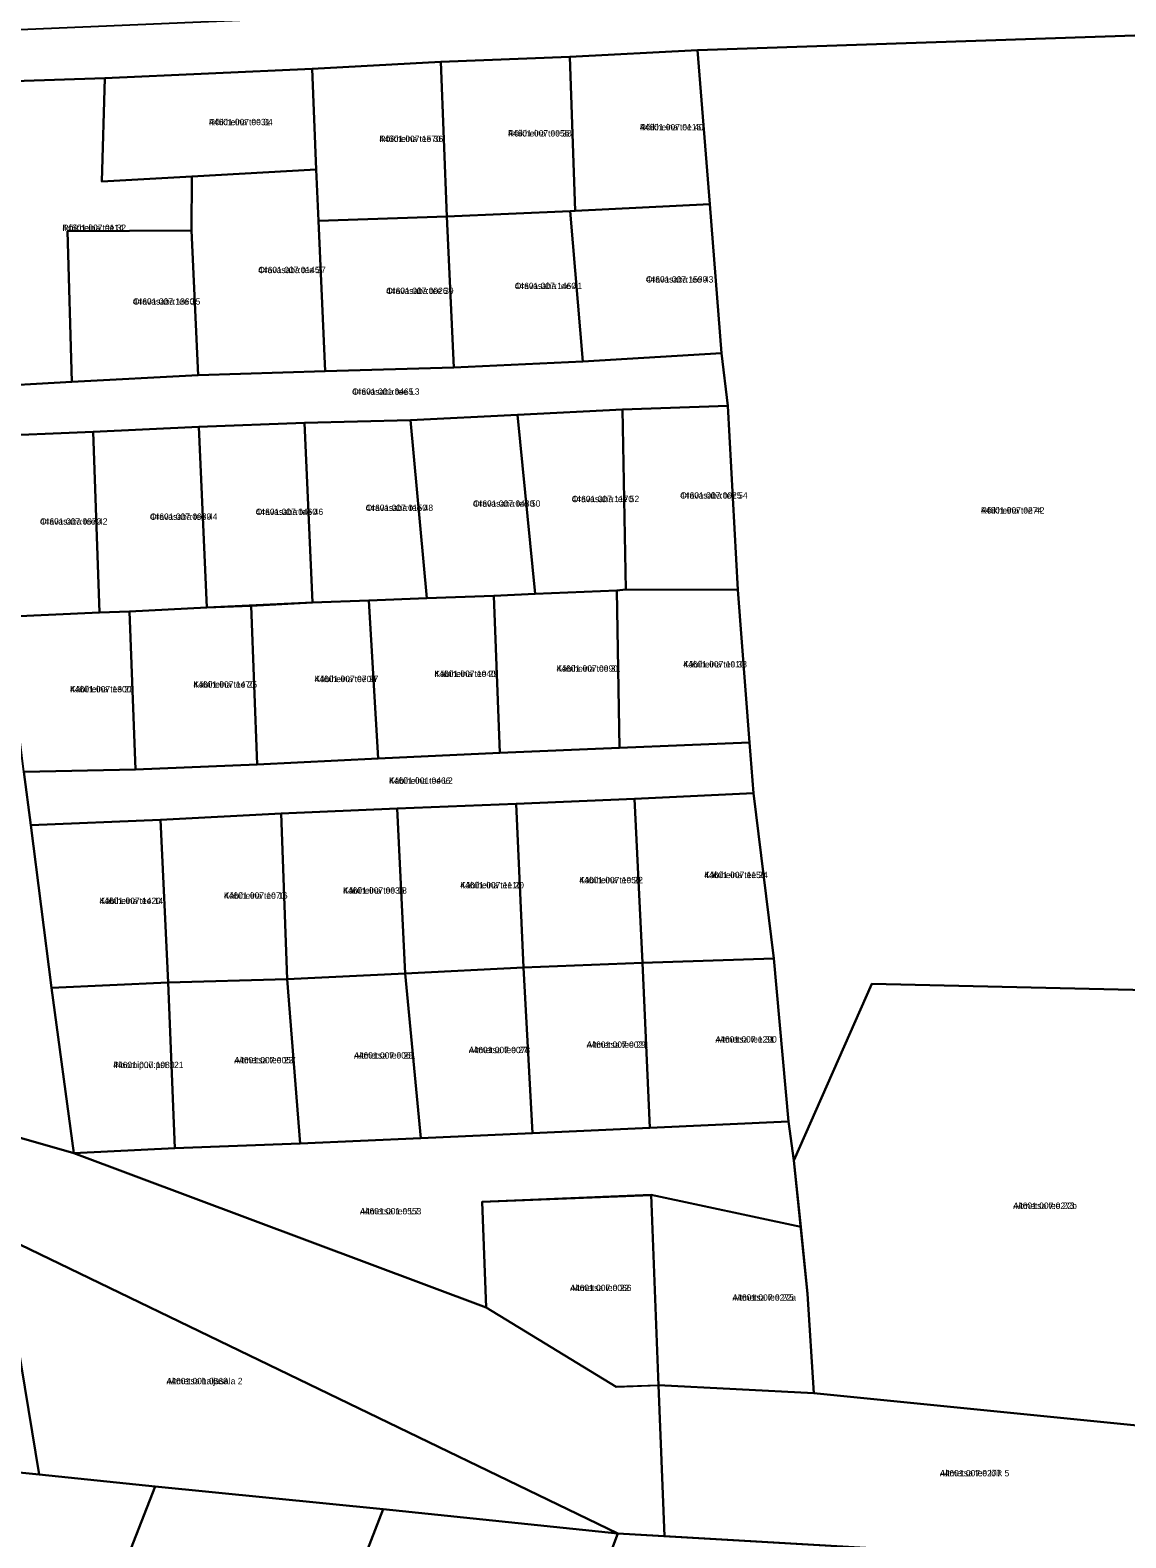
# Model space of a CAD drawing. Extents: x 551843 to 558501, y 6589003 to 6595718.
# Drawn here: x 554119.5 to 554378.5, y 6592353.3 to 6592709.8 of the extents above; entities that cross this region are included whole.
import ezdxf

# ---------------------------------------------------------------- set-up
doc = ezdxf.new("R2010")
doc.units = 0
for name, color, linetype in [('L_AADRESS', 7, 'Continuous'), ('PIIR', 7, 'Continuous'), ('TUNNUS', 7, 'Continuous')]:
    doc.layers.add(name, color=color, linetype=linetype)

msp = doc.modelspace()

# ---------------------------------------------------------------- linework, layer by layer
at = {"layer": 'PIIR'}
for points in [[(554096.53, 6592697.08), (554093.97, 6592709.01), (554118.91, 6592710.02), (554144.94, 6592711.06), (554170.97, 6592712.22), (554197.07, 6592713.42), (554222.84, 6592714.47), (554247.74, 6592715.45), (554276.46, 6592716.41), (554286.44, 6592717.06), (554411.66, 6592724.59), (554411.2, 6592709.5), (554277.28, 6592705.03), (554247.08, 6592703.49), (554216.6, 6592702.26), (554186.13, 6592700.61), (554137.12, 6592698.41)], [(554277.28, 6592705.03), (554411.2, 6592709.5), (554410.15, 6592675.78), (554409.09, 6592641.51), (554408.12, 6592610.02), (554407.21, 6592580.64), (554406.4, 6592554.65), (554405.5, 6592525.38), (554404.66, 6592498.07), (554404.12, 6592482.32), (554318.46, 6592484.32), (554300.06, 6592442.55), (554298.78, 6592451.79), (554295.27, 6592490.33), (554290.49, 6592529.36), (554289.57, 6592541.38), (554286.82, 6592577.47), (554284.43, 6592620.98), (554282.94, 6592633.43), (554280.18, 6592668.59)], [(554247.08, 6592703.49), (554277.28, 6592705.03), (554280.18, 6592668.59), (554248.31, 6592667.05)], [(554216.6, 6592702.26), (554217.99, 6592665.7), (554187.65, 6592664.68), (554187.14, 6592676.79), (554186.13, 6592700.61)], [(554247.08, 6592703.49), (554248.31, 6592667.05), (554247.18, 6592667), (554217.99, 6592665.7), (554216.6, 6592702.26)], [(554096.53, 6592697.08), (554137.12, 6592698.41), (554136.47, 6592673.96), (554157.71, 6592675.13), (554157.61, 6592662.43), (554128.31, 6592662.26), (554129.3, 6592626.64), (554106.93, 6592625.38)], [(554186.13, 6592700.61), (554187.14, 6592676.79), (554157.71, 6592675.13), (554136.47, 6592673.96), (554137.12, 6592698.41)], [(554157.71, 6592675.13), (554187.14, 6592676.79), (554187.65, 6592664.68), (554189.2, 6592629.11), (554159.22, 6592628.18), (554157.61, 6592662.43)], [(554217.99, 6592665.7), (554219.68, 6592630.05), (554189.2, 6592629.11), (554187.65, 6592664.68)], [(554247.18, 6592667), (554250.11, 6592631.39), (554219.68, 6592630.05), (554217.99, 6592665.7)], [(554247.18, 6592667), (554248.31, 6592667.05), (554280.18, 6592668.59), (554282.94, 6592633.43), (554250.11, 6592631.39)], [(554159.22, 6592628.18), (554129.3, 6592626.64), (554128.31, 6592662.26), (554157.61, 6592662.43)], [(554106.93, 6592625.38), (554129.3, 6592626.64), (554159.22, 6592628.18), (554189.2, 6592629.11), (554219.68, 6592630.05), (554250.11, 6592631.39), (554282.94, 6592633.43), (554284.43, 6592620.98), (554259.5, 6592620.05), (554234.71, 6592618.85), (554209.44, 6592617.55), (554184.38, 6592616.9), (554159.4, 6592615.97), (554134.35, 6592614.83), (554107.73, 6592613.69)], [(554234.71, 6592618.85), (554259.5, 6592620.05), (554260.33, 6592577.5), (554258.22, 6592577.32), (554238.9, 6592576.53)], [(554260.33, 6592577.5), (554259.5, 6592620.05), (554284.43, 6592620.98), (554286.82, 6592577.47)], [(554135.9, 6592572.1), (554134.35, 6592614.83), (554159.4, 6592615.97), (554161.26, 6592573.29), (554142.99, 6592572.29)], [(554184.38, 6592616.9), (554186.23, 6592574.42), (554161.26, 6592573.29), (554159.4, 6592615.97)], [(554184.38, 6592616.9), (554209.44, 6592617.55), (554213.23, 6592575.49), (554199.58, 6592574.95), (554186.23, 6592574.42)], [(554234.71, 6592618.85), (554238.9, 6592576.53), (554229.08, 6592576.05), (554213.23, 6592575.49), (554209.44, 6592617.55)], [(554107.73, 6592613.69), (554134.35, 6592614.83), (554135.9, 6592572.1), (554113.47, 6592571.05)], [(554229.08, 6592576.05), (554238.9, 6592576.53), (554258.22, 6592577.32), (554258.8, 6592540.07), (554230.56, 6592538.88)], [(554258.22, 6592577.32), (554260.33, 6592577.5), (554286.82, 6592577.47), (554289.57, 6592541.38), (554258.8, 6592540.07)], [(554142.99, 6592572.29), (554161.26, 6592573.29), (554171.71, 6592573.7), (554173.19, 6592536.18), (554144.4, 6592534.95)], [(554171.71, 6592573.7), (554186.23, 6592574.42), (554199.58, 6592574.95), (554201.74, 6592537.54), (554173.19, 6592536.18)], [(554199.58, 6592574.95), (554213.23, 6592575.49), (554229.08, 6592576.05), (554230.56, 6592538.88), (554201.74, 6592537.54)], [(554135.9, 6592572.1), (554142.99, 6592572.29), (554144.4, 6592534.95), (554117.98, 6592534.46), (554113.47, 6592571.05)], [(553717.39, 6592504.18), (553600.76, 6592522.67), (553604.12, 6592547.44), (553721.81, 6592527.78), (553764.18, 6592518.32), (553823.14, 6592505.15), (553854.04, 6592498.24), (553917.31, 6592484.11), (553947.26, 6592478.76), (553971.19, 6592474.49), (553993.07, 6592470.58), (554018, 6592466.14), (554042.28, 6592461.8), (554067.71, 6592457.27), (554112.49, 6592449.27), (554129.79, 6592444.29), (554227.28, 6592407.81), (554258.05, 6592389), (554268.05, 6592389.41), (554269.43, 6592353.75), (554258.46, 6592354.38), (554112.26, 6592424.94), (553921.13, 6592459.29), (553764.47, 6592494.01)], [(554117.98, 6592534.46), (554144.4, 6592534.95), (554173.19, 6592536.18), (554201.74, 6592537.54), (554230.56, 6592538.88), (554258.8, 6592540.07), (554289.57, 6592541.38), (554290.49, 6592529.36), (554262.4, 6592528.05), (554234.39, 6592526.89), (554206.23, 6592525.79), (554178.84, 6592524.56), (554150.34, 6592523.1), (554119.63, 6592521.81)], [(554234.39, 6592526.89), (554236.11, 6592488.14), (554208.12, 6592486.72), (554206.23, 6592525.79)], [(554234.39, 6592526.89), (554262.4, 6592528.05), (554264.23, 6592489.28), (554236.11, 6592488.14)], [(554290.49, 6592529.36), (554295.27, 6592490.33), (554264.23, 6592489.28), (554262.4, 6592528.05)], [(554150.34, 6592523.1), (554152.14, 6592484.61), (554124.57, 6592483.37), (554119.63, 6592521.81)], [(554178.84, 6592524.56), (554180.26, 6592485.4), (554152.14, 6592484.61), (554150.34, 6592523.1)], [(554206.23, 6592525.79), (554208.12, 6592486.72), (554180.26, 6592485.4), (554178.84, 6592524.56)], [(554236.11, 6592488.14), (554238.25, 6592449.04), (554211.85, 6592447.85), (554208.12, 6592486.72)], [(554264.23, 6592489.28), (554265.97, 6592450.28), (554238.25, 6592449.04), (554236.11, 6592488.14)], [(554298.78, 6592451.79), (554265.97, 6592450.28), (554264.23, 6592489.28), (554295.27, 6592490.33)], [(554153.67, 6592445.47), (554129.79, 6592444.29), (554124.57, 6592483.37), (554152.14, 6592484.61)], [(554180.26, 6592485.4), (554183.36, 6592446.56), (554153.67, 6592445.47), (554152.14, 6592484.61)], [(554208.12, 6592486.72), (554211.85, 6592447.85), (554183.36, 6592446.56), (554180.26, 6592485.4)], [(554300.06, 6592442.55), (554318.46, 6592484.32), (554404.12, 6592482.32), (554403.83, 6592473.91), (554403.14, 6592449.32), (554402.44, 6592426.65), (554400.93, 6592377.89), (554304.73, 6592387.52), (554303.28, 6592411)], [(554112.26, 6592424.94), (554121.63, 6592368.29), (554092.65, 6592371.24), (554037.34, 6592376.9), (553982.35, 6592382.45), (553931.99, 6592387.57), (553921.13, 6592459.29)], [(554129.79, 6592444.29), (554153.67, 6592445.47), (554183.36, 6592446.56), (554211.85, 6592447.85), (554238.25, 6592449.04), (554265.97, 6592450.28), (554298.78, 6592451.79), (554300.06, 6592442.55), (554301.66, 6592426.83), (554266.31, 6592434.4), (554226.31, 6592432.79), (554227.28, 6592407.81)], [(554268.04, 6592389.39), (554258.05, 6592389), (554227.28, 6592407.81), (554226.31, 6592432.79), (554266.28, 6592434.35)], [(554266.31, 6592434.4), (554301.66, 6592426.83), (554303.28, 6592411), (554304.73, 6592387.52), (554268.05, 6592389.41)], [(554258.46, 6592354.38), (554202.97, 6592360.09), (554149.03, 6592365.49), (554121.63, 6592368.29), (554112.26, 6592424.94)], [(554268.05, 6592389.41), (554304.73, 6592387.52), (554400.93, 6592377.89), (554400.72, 6592371.06), (554397.18, 6592346.36), (554269.43, 6592353.75)], [(554092.65, 6592371.24), (554121.63, 6592368.29), (554149.03, 6592365.49), (554023.98, 6592045.41), (553969.48, 6592053.3)], [(554149.03, 6592365.49), (554202.97, 6592360.09), (554074.47, 6592028.38), (554023.98, 6592045.41)], [(554202.97, 6592360.09), (554258.46, 6592354.38), (554162.16, 6592098.06), (554138.38, 6592009.57), (554074.47, 6592028.38)], [(554371.01, 6592256.08), (554228.71, 6592275.2), (554258.46, 6592354.38), (554397.18, 6592346.36)]]:
    msp.add_lwpolyline(points, close=True, dxfattribs=at)
msp.add_lwpolyline([(554117.98, 6592534.46), (554119.63, 6592521.81), (554124.57, 6592483.37), (554129.79, 6592444.29), (554112.49, 6592449.27)], dxfattribs=at)

# ---------------------------------------------------------------- texts
at = {"layer": 'L_AADRESS'}
for s, p in [('Rõikheina tee 34', (554161.76, 6592687.29)), ('Rõikheina tee 40', (554263.63, 6592686.06)), ('Rõikheina tee 36', (554202.06, 6592683.32)), ('Rõikheina tee 38', (554232.46, 6592684.62)), ('Rõikheina tee 32', (554127.12, 6592662.3)), ('Oravasaba tee 37', (554173.41, 6592652.32)), ('Oravasaba tee 43', (554265.06, 6592650.09)), ('Oravasaba tee 39', (554203.66, 6592647.39)), ('Oravasaba tee 41', (554234.05, 6592648.55)), ('Oravasaba tee 35', (554143.77, 6592644.87)), ('Oravasaba tee L3', (554195.59, 6592623.56)), ('Oravasaba tee 50', (554224.17, 6592597.09)), ('Oravasaba tee 52', (554247.52, 6592598.18)), ('Oravasaba tee 54', (554273.16, 6592599.02)), ('Oravasaba tee 42', (554121.81, 6592592.87)), ('Oravasaba tee 44', (554147.8, 6592594)), ('Oravasaba tee 46', (554172.81, 6592595.14)), ('Oravasaba tee 48', (554198.8, 6592596.1)), ('Rõikheina tee 42', (554344.24, 6592595.49)), ('Käbiheina tee 31', (554243.94, 6592558.09)), ('Käbiheina tee 33', (554273.89, 6592559.1)), ('Käbiheina tee 25', (554158.09, 6592554.33)), ('Käbiheina tee 27', (554186.73, 6592555.63)), ('Käbiheina tee 29', (554215.07, 6592556.86)), ('Käbiheina tee 23', (554128.93, 6592553.22)), ('Käbiheina tee L2', (554204.34, 6592531.59)), ('Käbiheina tee 22', (554249.31, 6592508.09)), ('Käbiheina tee 24', (554278.84, 6592509.3)), ('Käbiheina tee 16', (554165.3, 6592504.42)), ('Käbiheina tee 18', (554193.48, 6592505.62)), ('Käbiheina tee 20', (554221.17, 6592506.88)), ('Käbiheina tee 14', (554135.89, 6592503.19)), ('Altmetsa tee 29', (554251.04, 6592469.18)), ('Altmetsa tee 31', (554281.5, 6592470.43)), ('Altmetsa tee 23', (554167.75, 6592465.52)), ('Altmetsa tee 25', (554196.05, 6592466.64)), ('Altmetsa tee 27', (554223.18, 6592467.92)), ('Ploomipuu pst 121', (554139.12, 6592464.39)), ('Altmetsa tee L7', (554197.47, 6592429.8)), ('Altmetsa tee 22b', (554351.9, 6592431.11)), ('Altmetsa tee 22', (554247.15, 6592411.68)), ('Altmetsa tee 22a', (554285.52, 6592409.4)), ('Altmetsa haljasala 2', (554151.73, 6592389.66)), ('Altmetsa tee lõik 5', (554334.57, 6592367.88))]:
    msp.add_text(s, height=1.5, dxfattribs=at).set_placement(p)
at = {"layer": 'TUNNUS'}
for s, p in [('44601:007:0031', (554161.76, 6592687.29)), ('44601:007:0116', (554263.63, 6592686.06)), ('44601:007:1570', (554202.06, 6592683.32)), ('44601:007:0056', (554232.46, 6592684.62)), ('44601:007:0114', (554127.12, 6592662.3)), ('44601:007:0145', (554173.41, 6592652.32)), ('44601:007:1590', (554265.06, 6592650.09)), ('44601:007:0026', (554203.66, 6592647.39)), ('44601:007:1460', (554234.05, 6592648.55)), ('44601:007:1360', (554143.77, 6592644.87)), ('44601:001:0465', (554195.59, 6592623.56)), ('44601:007:0430', (554224.17, 6592597.09)), ('44601:007:1170', (554247.52, 6592598.18)), ('44601:007:0025', (554273.16, 6592599.02)), ('44601:007:0970', (554121.81, 6592592.87)), ('44601:007:0980', (554147.8, 6592594)), ('44601:007:0460', (554172.81, 6592595.14)), ('44601:007:0150', (554198.8, 6592596.1)), ('44601:007:0274', (554344.24, 6592595.49)), ('44601:007:0990', (554243.94, 6592558.09)), ('44601:007:1010', (554273.89, 6592559.1)), ('44601:007:1470', (554158.09, 6592554.33)), ('44601:007:0700', (554186.73, 6592555.63)), ('44601:007:1040', (554215.07, 6592556.86)), ('44601:007:1300', (554128.93, 6592553.22)), ('44601:001:0466', (554204.34, 6592531.59)), ('44601:007:1050', (554249.31, 6592508.09)), ('44601:007:1150', (554278.84, 6592509.3)), ('44601:007:1070', (554165.3, 6592504.42)), ('44601:007:0035', (554193.48, 6592505.62)), ('44601:007:1110', (554221.17, 6592506.88)), ('44601:007:1420', (554135.89, 6592503.19)), ('44601:007:0022', (554251.04, 6592469.18)), ('44601:007:1290', (554281.5, 6592470.43)), ('44601:007:0057', (554167.75, 6592465.52)), ('44601:007:0061', (554196.05, 6592466.64)), ('44601:007:0078', (554223.18, 6592467.92)), ('44601:007:1080', (554139.12, 6592464.39)), ('44601:001:0553', (554197.47, 6592429.8)), ('44601:007:0273', (554351.9, 6592431.11)), ('44601:007:0066', (554247.15, 6592411.68)), ('44601:007:0275', (554285.52, 6592409.4)), ('44601:001:0568', (554151.73, 6592389.66)), ('44601:007:0277', (554334.57, 6592367.88))]:
    msp.add_text(s, height=1.5, dxfattribs=at).set_placement(p)

doc.saveas('drawing.dxf')
